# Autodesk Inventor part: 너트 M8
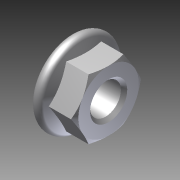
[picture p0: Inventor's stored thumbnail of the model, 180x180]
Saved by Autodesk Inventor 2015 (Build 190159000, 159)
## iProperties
Created: 2025-08
Part Number: 너트 M8
Material: 일반
Document SubType Name: Modeling
Designer: USER
Density: 1 g/cm^3
Appearance: 기본값
Author: USER
Author: jhkim
Description: 플랜지붙이 6각 너트 - 일반 스레드
Creation Date: 2025-08-05
Sending System: Autodesk Inventor 2026
Preprocessor: ST-DEVELOPER v20.1
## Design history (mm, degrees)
node "너트 M81"
body "Solid1"
node "기준1"
